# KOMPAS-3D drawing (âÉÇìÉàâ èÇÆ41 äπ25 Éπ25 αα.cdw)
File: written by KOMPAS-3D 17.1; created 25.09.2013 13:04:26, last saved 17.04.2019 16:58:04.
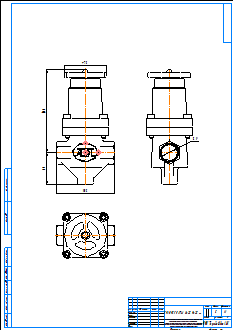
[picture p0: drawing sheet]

Sheet 1: A2, portrait

Title block, sheet 1: name: ГРАНРЕГ КАТ41 Ду25 Ру25 рр; material: Внимание! Данный продукт является объектом авторского права ООО «Торговый Дом АДЛ». / Запрещается изменение, копирование, распространение / (в том числе путем копирования на другие сайты и ресурсы в Интернете) / или любое иное использование информации и объектов без предварительного / согласия правообладателя (ООО «Торговый Дом АДЛ»).; mass: 5; sheets: 1; organisation: ООО "Торговый дом АДЛ"; sheet format: A2; stored path: \\adlc.lan\data\АДЛ_ПКД\3D-модели\ADL production\Клапаны КАТ ГРАНРЕГ\КАТ41\KOMPAS 2D\ГРАНРЕГ КАТ41 Ду25 Ру25 рр.cdw

Views: Вид 1
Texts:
  Klimkovich
  ADL
Dimensions and other numbers on the sheet: 75; 105; 150; 57; 1:1; 1; 5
